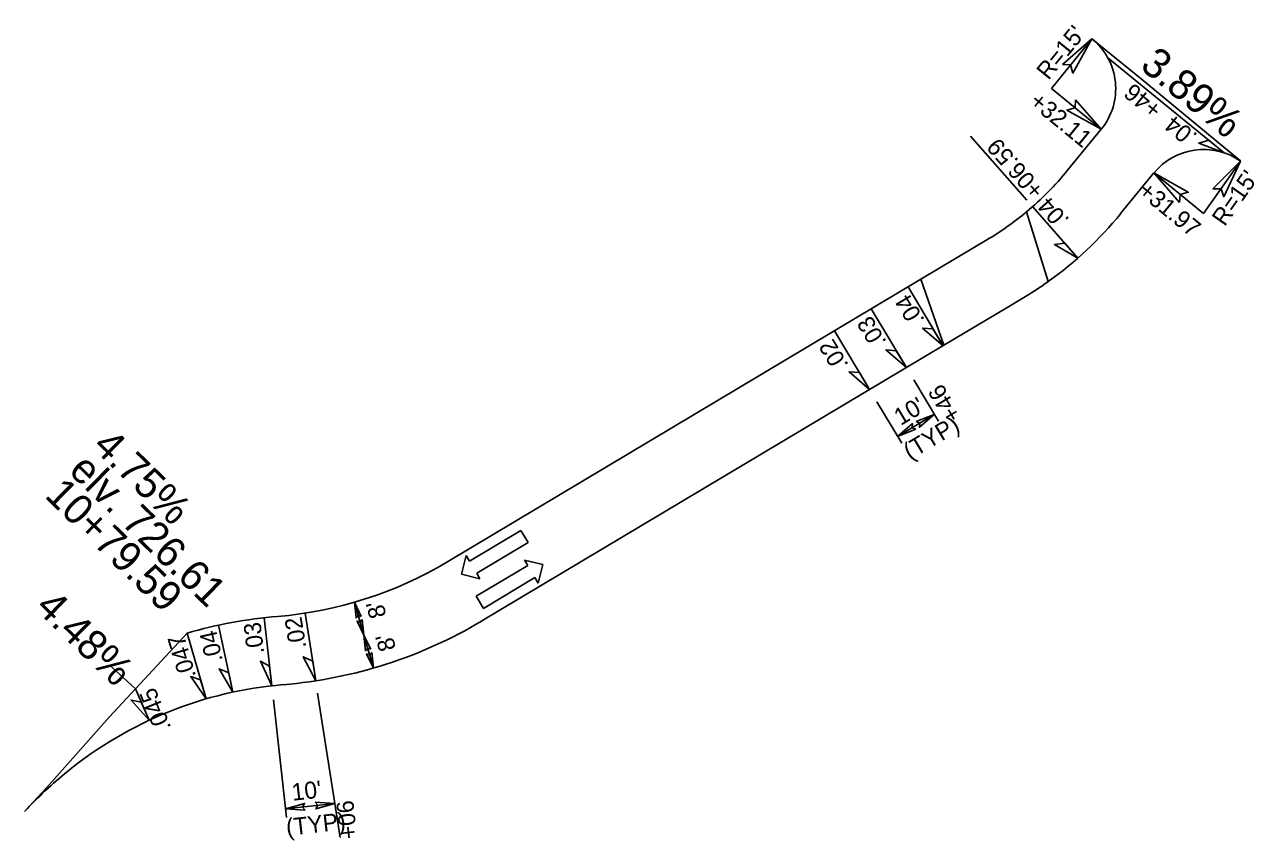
# Model space of a CAD drawing. Extents: x 1487977 to 1520121, y 473151 to 500023.
# Drawn here: x 1488395 to 1488682.2, y 499068.5 to 499259.2 of the extents above; entities that cross this region are included whole.
import ezdxf

# ---------------------------------------------------------------- set-up
doc = ezdxf.new("R2010")
doc.units = 0
for name, color, linetype in [('Prop CMT Corridor Exterior Boundary', 7, 'Continuous'), ('Prop CMT Slope Fill', 7, 'Continuous'), ('Prop Dimension Text', 7, 'Continuous'), ('Prop EOT Dash', 7, 'Continuous'), ('Prop SS Cut Text', 7, 'Continuous'), ('Prop SS Fill Text', 7, 'Continuous'), ('Prop Superelevation  Arrow CELL', 7, 'Continuous'), ('Prop Superelevation Label', 7, 'Continuous'), ('Sheet Sticker Exception Certification CELL', 7, 'Continuous')]:
    doc.layers.add(name, color=color, linetype=linetype)

msp = doc.modelspace()

# ---------------------------------------------------------------- linework, layer by layer
at = {"layer": 'Prop CMT Corridor Exterior Boundary'}
for p, q in [((1488644.26, 499255.86), (1488634.82, 499244.21)), ((1488646.43, 499234.72), (1488634.82, 499244.21)), ((1488678.94, 499227.29), (1488670.35, 499214.99)), ((1488658.73, 499224.49), (1488670.35, 499214.99)), ((1488472.04, 499124.18), (1488474.27, 499116.49)), ((1488474.27, 499116.49), (1488476.49, 499108.81))]:
    msp.add_line(p, q, dxfattribs=at)
at = {"layer": 'Prop CMT Slope Fill'}
msp.add_line((1488420.93, 499103.94), (1488415.3, 499109.11), dxfattribs=at)
at = {"layer": 'Prop EOT Dash'}
for p, q in [((1488628.96, 499215.4), (1488634.02, 499199.1)), ((1488604.33, 499199.66), (1488616.45, 499206.9)), ((1488616.45, 499206.9), (1488619.75, 499208.87)), ((1488604.33, 499199.66), (1488609.7, 499184.23)), ((1488624.66, 499193.16), (1488627.95, 499195.13)), ((1488609.7, 499184.23), (1488624.66, 499193.16))]:
    msp.add_line(p, q, dxfattribs=at)
for radius, end in [(72, 309.8335), (88, 305.5637)]:
    msp.add_arc((1488582.84, 499270.69), radius, 300.8418, end, dxfattribs=at)
at = {"layer": 'Prop SS Cut Text'}
for p, q in [((1488498.9, 499133.81), (1488510.92, 499140.98)), ((1488510.92, 499140.98), (1488512.61, 499138.15)), ((1488512.61, 499138.15), (1488500.59, 499130.97)), ((1488497.07, 499130.73), (1488498.13, 499135.09)), ((1488498.13, 499135.09), (1488498.9, 499133.81)), ((1488500.49, 499125.59), (1488512.51, 499132.76)), ((1488512.51, 499132.76), (1488511.74, 499134.05)), ((1488511.74, 499134.05), (1488516.04, 499133)), ((1488516.04, 499133), (1488514.97, 499128.64)), ((1488501.36, 499129.69), (1488497.07, 499130.73)), ((1488500.59, 499130.97), (1488501.36, 499129.69)), ((1488514.2, 499129.93), (1488502.18, 499122.75)), ((1488514.97, 499128.64), (1488514.2, 499129.93)), ((1488502.18, 499122.75), (1488500.49, 499125.59))]:
    msp.add_line(p, q, dxfattribs=at)
at = {"layer": 'Prop SS Fill Text'}
for points in [[(1488637.39, 499249.85), (1488644.26, 499255.86), (1488639.81, 499247.82), (1488639.29, 499249.73)], [(1488640.44, 499241.61), (1488646.43, 499234.72), (1488638.41, 499239.21), (1488640.31, 499239.72)], [(1488672.51, 499220.8), (1488678.94, 499227.29), (1488675.06, 499218.95), (1488674.41, 499220.81)], [(1488664.72, 499217.59), (1488658.73, 499224.49), (1488666.75, 499220), (1488664.85, 499219.49)], [(1488473.64, 499120.89), (1488472.04, 499124.18), (1488472.43, 499120.52), (1488472.92, 499121.14)], [(1488473.86, 499120.12), (1488474.27, 499116.49), (1488472.65, 499119.79), (1488473.39, 499119.53)], [(1488475.86, 499113.21), (1488474.27, 499116.49), (1488474.66, 499112.84), (1488475.15, 499113.46)], [(1488476.09, 499112.44), (1488476.49, 499108.81), (1488474.87, 499112.11), (1488475.61, 499111.84)]]:
    msp.add_lwpolyline(points, close=True, dxfattribs=at)
at = {"layer": 'Prop Superelevation  Arrow CELL'}
for p, q in [((1488647.99, 499251.38), (1488675.11, 499229.22)), ((1488629.07, 499218.13), (1488615.94, 499233.06)), ((1488630.39, 499216.63), (1488640.96, 499204.61)), ((1488601.32, 499197.86), (1488609.53, 499184.13)), ((1488592.74, 499192.74), (1488600.94, 499179)), ((1488584.15, 499187.61), (1488592.35, 499173.87)), ((1488608.43, 499166.46), (1488602.65, 499176.14)), ((1488599.84, 499161.33), (1488594.06, 499171.01)), ((1488607.46, 499168.07), (1488598.88, 499162.95)), ((1488450.95, 499120.56), (1488452.74, 499104.66)), ((1488460.56, 499121.64), (1488463.01, 499105.83)), ((1488440.3, 499118.82), (1488443.67, 499103.18)), ((1488432.97, 499116.97), (1488437.42, 499101.6)), ((1488420.93, 499103.94), (1488424.1, 499096.6)), ((1488456.2, 499073.89), (1488453.12, 499101.35)), ((1488468.68, 499069.22), (1488463.45, 499102.95)), ((1488467.45, 499077.17), (1488455.98, 499075.88))]:
    msp.add_line(p, q, dxfattribs=at)
for points in [[(1488675.11, 499229.22), (1488669.2, 499231.47), (1488671.53, 499232.14)], [(1488640.96, 499204.61), (1488635.5, 499207.8), (1488637.91, 499208.09)], [(1488609.53, 499184.13), (1488604.73, 499188.25), (1488607.15, 499188.1)], [(1488600.94, 499179), (1488596.15, 499183.13), (1488598.57, 499182.97)], [(1488592.35, 499173.87), (1488587.56, 499178), (1488589.98, 499177.84)], [(1488603.2, 499166.43), (1488607.46, 499168.07), (1488603.99, 499165.07), (1488604.07, 499166.05)], [(1488603.14, 499164.59), (1488598.88, 499162.95), (1488602.35, 499165.95), (1488602.27, 499164.97)], [(1488452.74, 499104.66), (1488450.08, 499110.4), (1488452.23, 499109.26)], [(1488463.01, 499105.83), (1488460.11, 499111.45), (1488462.3, 499110.4)], [(1488437.42, 499101.6), (1488433.83, 499106.81), (1488436.13, 499106.04)], [(1488443.67, 499103.18), (1488440.45, 499108.62), (1488442.69, 499107.7)], [(1488424.1, 499096.6), (1488419.89, 499101.31), (1488422.27, 499100.84)], [(1488462.89, 499077.44), (1488467.45, 499077.17), (1488463.04, 499075.87), (1488463.52, 499076.73)], [(1488460.54, 499075.61), (1488455.98, 499075.88), (1488460.39, 499077.18), (1488459.91, 499076.32)]]:
    msp.add_lwpolyline(points, close=True, dxfattribs=at)
at = {"layer": 'Sheet Sticker Exception Certification CELL'}
for p, q in [((1488638.58, 499225.12), (1488646.43, 499234.72)), ((1488650.97, 499214.99), (1488658.73, 499224.49)), ((1488493.63, 499133.56), (1488604.33, 499199.66)), ((1488501.83, 499119.82), (1488609.7, 499184.23))]:
    msp.add_line(p, q, dxfattribs=at)
for points in [[(1488644.26, 499255.86), (1488655.78, 499246.53), (1488675.03, 499230.53), (1488678.96, 499227.32)], [(1488432.97, 499116.97), (1488414.86, 499097.38), (1488400.17, 499080.83), (1488395.02, 499075.32)]]:
    msp.add_lwpolyline(points, dxfattribs=at)
for centre, radius, start, end in [((1488634.82, 499244.21), 15, 320.7375, 50.9704), ((1488670.35, 499214.99), 15, 55.0649, 140.7375), ((1488582.84, 499270.69), 72, 309.8335, 320.7375), ((1488582.84, 499270.69), 88, 305.5637, 320.7375), ((1488446.47, 499212.55), 92, 274.7509, 300.8418), ((1488463.03, 499013.24), 108, 94.7509, 106.1619), ((1488446.47, 499212.55), 108, 274.7509, 300.8418), ((1488463.03, 499013.24), 92, 94.7509, 129.0794), ((1488468.07, 499007.03), 100, 129.0794, 136.9313)]:
    msp.add_arc(centre, radius, start, end, dxfattribs=at)

# ---------------------------------------------------------------- texts
at = {"layer": 'Prop CMT Slope Fill'}
for s, rotation, p in [('3.89%', 320.7383, (1488655.21, 499249.06)), ('4.75%', 315.6825, (1488410.64, 499160.32)), ('elv. 726.61', 315.6825, (1488405.05, 499154.59)), ('10+79.59', 315.6825, (1488399.46, 499148.87)), ('4.48%', 315.6825, (1488397.25, 499122.67))]:
    msp.add_text(s, height=7, rotation=rotation, dxfattribs=at).set_placement(p)
at = {"layer": 'Prop Dimension Text'}
for s, rotation, p in [("R=15'", 50.9704, (1488634.09, 499246.02)), ('+32.11', 320.5687, (1488629.41, 499240.65)), ("R=15'", 55.0649, (1488675.27, 499211.83)), ('+31.97', 320.5687, (1488654.79, 499219.77)), ("8'", 106.1419, (1488479.58, 499121.08)), ("8'", 106.1419, (1488481.8, 499113.39))]:
    msp.add_text(s, height=4, rotation=rotation, dxfattribs=at).set_placement(p)
at = {"layer": 'Prop Superelevation  Arrow CELL'}
for s, rotation, p in [('+46', 140.8036, (1488660.94, 499239.96)), ('.04', 140.8036, (1488669.14, 499233.44)), ('+06.59', 131.5744, (1488633.35, 499220.64)), ('.04', 131.5743, (1488639.19, 499213.64)), ('.04', 121.0763, (1488605.32, 499190.18)), ('.03', 121.0763, (1488596.44, 499185.06)), ('.02', 121.0763, (1488587.56, 499179.66)), ("10'", 30.8418, (1488599.58, 499165.35)), ('(TYP)', 30.8418, (1488601.77, 499157.34)), ('.02', 99.0454, (1488460.82, 499113.65)), ('.03', 96.6552, (1488450.96, 499112.32)), ('.047', 106.3964, (1488435.09, 499106.95)), ('.04', 102.3848, (1488441.32, 499110.61)), ('.045', 112.2314, (1488429.33, 499094.91)), ("10'", 6.4206, (1488457.61, 499077.78)), ('(TYP)', 6.4206, (1488456.3, 499069.58))]:
    msp.add_text(s, height=4, rotation=rotation, dxfattribs=at).set_placement(p)
at = {"layer": 'Prop Superelevation Label'}
for s, rotation, p in [('+46', 120.8418, (1488613.88, 499167.7)), ('+06', 96.4206, (1488472.75, 499069.04))]:
    msp.add_text(s, height=4, rotation=rotation, dxfattribs=at).set_placement(p)

doc.saveas('drawing.dxf')
